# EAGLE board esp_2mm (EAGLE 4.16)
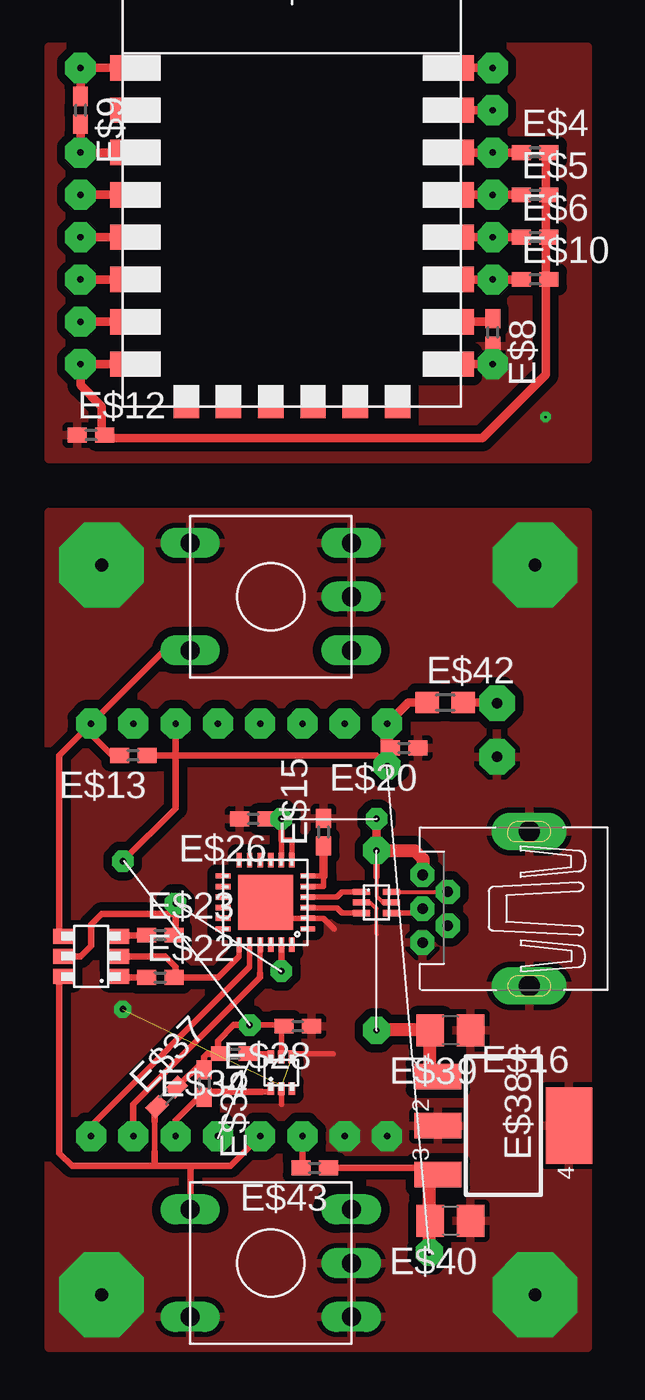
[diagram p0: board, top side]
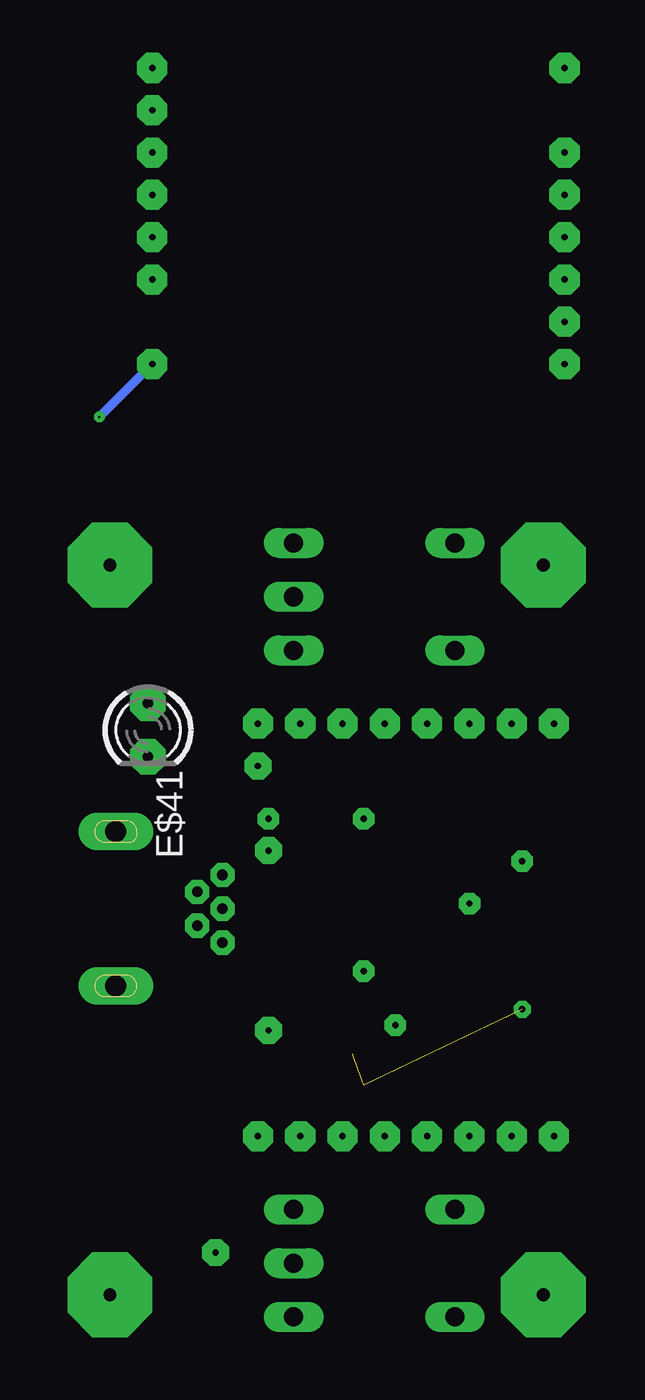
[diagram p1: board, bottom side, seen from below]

No outline drawn. Coordinates in mm, seen from the top.
Copper layers (1*16): Top 0.035mm / dielectric 1.5mm / Bottom 0.035mm
Design rules "default": minimum track width 10mil, minimum drill 24mil, track to track 8mil, track to pad 8mil, pad to pad 8mil, via to via 8mil, smd to smd 8mil, copper to edge 40mil, drill to drill 8mil, minimum pad ring 10mil, minimum via ring 8mil, stop-mask expansion 4mil, vias tented up to drill 0mil, thermal gap 10mil

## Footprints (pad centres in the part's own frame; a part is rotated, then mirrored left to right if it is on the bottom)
12E = smd 2.4 x 1.2: P$1 0.6,16; P$2 0.6,14; P$3 0.6,12; P$4 0.6,10; P$5 0.6,8; P$6 0.6,6; P$7 0.6,4; P$8 0.6,2; P$9 15.4,16; P$10 15.4,14; P$11 15.4,12; P$12 15.4,10; P$13 15.4,8; P$14 15.4,6; P$15 15.4,4; P$16 15.4,2 | smd 1.2 x 1.5: P$17 3,0.2; P$18 5,0.2; P$19 7,0.2; P$20 9,0.2; P$21 11,0.2; P$22 13,0.2
C0402 = smd 0.9 x 0.7: 1 -0.65,0; 2 0.65,0
QFN24 = smd 0.7 x 0.25: 1 -2,1.25; 2 -2,0.75; 3 -2,0.25; 4 -2,-0.25; 5 -2,-0.75; 6 -2,-1.25; 13 2,-1.25; 14 2,-0.75; 15 2,-0.25; 16 2,0.25; 17 2,0.75; 18 2,1.25 | smd 0.25 x 0.7: 7 -1.25,-2; 8 -0.75,-2; 9 -0.25,-2; 10 0.25,-2; 11 0.75,-2; 12 1.25,-2; 19 1.25,2; 20 0.75,2; 21 0.25,2; 22 -0.25,2; 23 -0.75,2; 24 -1.25,2 | smd 2.6 x 2.6: EP 0,0
32005-601 = drill 0.5 pad 1.15 octagon: 1 2.825,1.6; 2 1.625,0.8; 3 2.825,0; 4 1.625,-0.8; 5 2.825,-1.6 | drill 1 pad 1.778 long: M1 -2.225,3.65; M2 -2.225,-3.65
SUPERSOT-6 = smd 0.7 x 1: P$1 -0.95,1.3; P$2 0,1.3; P$3 0.95,1.3; P$4 -0.95,-1.3; P$5 0,-1.3; P$6 0.95,-1.3
SOT666 = smd 0.3 x 0.8: 1 0.5,0.7; 2 0,0.7; 3 -0.5,0.7; 4 -0.5,-0.7; 5 0,-0.7; 6 0.5,-0.7
SW_TACT_KSCL = drill 0.9 long: 1 -3.81,2.54; 2 -3.81,-2.54; 3 3.81,-2.54; 4 3.81,2.54; 5 -3.81,0
SOT563 = smd 0.3 x 0.6: 1 -0.5,-0.75; 2 0,-0.75; 3 0.5,-0.75; 4 0.5,0.75; 5 0,0.75; 6 -0.5,0.75
SOT223 = smd 1.219 x 2.235: 1 -2.311,-3.099; 2 0,-3.099; 3 2.311,-3.099 | smd 3.6 x 2.2: 4 0,3.099
C0805 = smd 1.3 x 1.5: 1 -0.95,0; 2 0.95,0
LED3MM = drill 0.5 pad 1.676 octagon: A -1.27,0; K 1.27,0
R0603 = smd 1.1 x 1: 1 -0.85,0; 2 0.85,0

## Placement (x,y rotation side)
E$3  [12E]  3.5,45 0 top
E$4  [C0402]  23,57 0 top
E$5  [C0402]  23,55 0 top
E$6  [C0402]  23,53 0 top
E$8  [C0402]  21,48.5 270 top
E$9  [C0402]  1.5,59 270 top
E$10  [C0402]  23,51 0 top
E$12  [C0402]  2,43.65 0 top
E$13  [C0402]  4,28.5 180 top
E$14  [QFN24]  10.25,21.55 180 top
E$15  [C0402]  13,24.88 90 top
E$16  [32005-601]  20.5,21.25 180 top
E$20  [C0402]  16.8,28.85 180 top
E$21  [SUPERSOT-6]  2,19 90 top
E$22  [C0402]  5.28,18 0 top
E$23  [C0402]  5.28,20 0 top
E$24  [SOT666]  15.5,21.55 90 top
E$25  [SW_TACT_KSCL]  10.5,4.5 180 top
E$26  [C0402]  9.68,25.5 180 top
E$27  [SOT563]  11,13.5 0 top
E$28  [C0402]  11.78,15.7 180 top
E$34  [C0402]  8.78,14.4 180 top
E$35  [C0402]  7.35,12.97 270 top
E$36  [SW_TACT_KSCL]  10.5,36 180 top
E$37  [C0402]  5.58,12.36 45 top
E$38  [SOT223]  21.5,11 270 top
E$39  [C0805]  19,15.5 180 top
E$40  [C0805]  19,6.5 180 top
E$41  [LED3MM]  21.2,29.7 270 bottom
E$42  [R0603]  18.75,31 0 top
E$43  [C0402]  12.57,9 180 top

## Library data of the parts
E$3 = esp8266
E$4-E$6 E$8-E$10 E$12 E$13 E$15 E$20 E$22 E$23 E$26 E$28 E$34 E$35 E$37-E$40 E$42 E$43 = ref-packages
E$14 = silabs
E$16 = con-cypressindustries
E$21 E$25 E$36 = sb
E$24 = st-microelectronics
E$27 = texas
E$41 = led

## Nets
GND1: E$8.2 E$12.1
GND2: E$15.2 E$16.1 E$16.M1 E$16.M2 E$20.1 E$25.1 E$25.4 E$25.5 E$26.2 E$28.1 E$36.2 E$36.3 E$36.5 E$38.2 E$38.4 E$39.1 E$40.1 E$41.K

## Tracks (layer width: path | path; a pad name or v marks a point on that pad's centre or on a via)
GND1  (via drill 0.1 pad 0.3, 0.3 pad 1.42)
  Top 0.305: v21,47 21,48
  Top 0.406: 19,47 v21,47
  Bottom 0.406: v21,47 v23.5,44.5
  pour Top (isolate 0.406): 0,42.5 25.5,42.5 25.5,62 0,62
GND2  (via drill 0.3 pad 0.81, 0.3 pad 1.42, 0.6 pad 4)  (2 unrouted)
  Top 0.2: 14.62,21.55 15.2,21.55 15.5,21.25 15.5,20.05
  Top 0.254: 11,12 11,12.9 | 13.5,20.3 13,20.8 11,20.8 | 11.55,14.4 13.45,14.4
  other vias: 2.5,3 14,10.5 16,10.5 23,3 2.5,37.5 23,37.5 3.5,16.5
  pour Top (isolate 0.406): 25.5,0.5 25.5,40 0,40 0,0.5
S$1  (via drill 0.3 pad 1.42)
  Top 0.406: 19,61 v21,61
S$7  (via drill 0.3 pad 1.42)
  Top 0.406: 19,59 v21,59
S$8  (via drill 0.3 pad 1.42)
  other vias: 21,57
S$9  (via drill 0.3 pad 1.42)
  other vias: 21,55
S$10  (via drill 0.3 pad 1.42)
  Top 0.406: v1.5,49 3.5,49
S$11  (via drill 0.3 pad 1.42)
  Top 0.406: 4,61 v1.5,61 1.5,60
S$12
  Top 0.406: 19.5,49 21,49
S$13
  Top 0.406: 19.5,53 22.5,53
S$14
  Top 0.406: 19.5,55 22,55
S$15
  Top 0.406: 19.5,57 22,57
S$16
  Top 0.406: 19,51 22,51
S$17  (via drill 0.3 pad 1.42)
  Top 0.406: 23.5,57 23.5,46.5 20.5,43.5 2.5,43.5 2.5,45 1.5,46 v1.5,47 4,47
S$18
  Top 0.406: 1.5,57 4,57
S$19  (via drill 0.3 pad 1.42)
  Top 0.406: v1.5,57 1.5,58
S$20  (via drill 0.3 pad 1.42)
  Top 0.406: v1.5,55 3.5,55
S$21  (via drill 0.3 pad 1.42)
  other vias: 21,53
S$22  (via drill 0.3 pad 1.42)
  other vias: 21,51
S$23  (via drill 0.3 pad 1.42)
  Top 0.406: v1.5,53 3.5,53
S$24  (via drill 0.3 pad 1.42)
  Top 0.406: v1.5,51 3.5,51
S$25  (via drill 0.3 pad 1.42)
  other vias: 2,30
S$27
  Top 0.305: 6,20 6,21.5
S$28
  Top 0.305: 2,30 2,29.5 3,28.5 3.5,28.5 | 0.5,20 0.5,28.5 2,30 | 2,30 5.5,33.5 7,33.5
S$29  (via drill 0.3 pad 1.42)
  other vias: 8,30
S$30  (via drill 0.3 pad 1.42)
  other vias: 14,30
S$31  (via drill 0.3 pad 1.02, 0.3 pad 1.27)
  Top 0.2: 16.25,21.55 15.8,21.55 15.5,21.85 15.5,22.75
  Top 0.305: 15.5,22.75 v15.5,24
  Top 0.406: v15.5,24 v15.5,25.5
  Top 0.61: v15.5,24 17.3,24 17.7,23.6 17.7,22.95
S$32
  Top 0.305: 4.5,20 3.5,20
S$33
  Top 0.254: 10,18.2 10,19.5
  Top 0.305: 4,10.5 4,12 10,18 10,18.2
S$34
  Top 0.254: 12.5,21.3 13.62,21.3 13.88,21.05 14.62,21.05
S$35
  Top 0.254: 12.5,21.8 13.62,21.8 13.88,22.05 14.62,22.05
S$36
  Top 0.254: 17.7,21.05 16.25,21.05
S$37
  Top 0.2: 16.38,22.05 18.82,22.05
S$38  (via drill 0.3 pad 1.42)
  Top 0.254: 10.1,12.6 10.45,12.6
  Top 0.305: v6,10.5 6,11.25 7.1,12.35 7.35,12.35 7.35,12.6 10.1,12.6
S$39  (via drill 0.3 pad 1.42)
  other vias: 4,10.5
S$42  (via drill 0.3 pad 1.42)
  other vias: 10,30
S$43  (via drill 0.3 pad 1.42)
  other vias: 12,30
S$44  (via drill 0.3 pad 1.42)
  other vias: 10,10.5
S$45  (via drill 0.3 pad 1.42)
  Top 0.305: 12,9 v12,10.5
S$46
  Top 0.305: 4.5,18 3.5,18
S$47
  Top 0.254: 11,24.5 11,23.8
  Top 0.305: 11,24.5 11,25.5
S$48  (via drill 0.3 pad 1.02)
  other vias: 11,25.5
S$49
  Top 0.254: 9.4,18.4 9.5,18.5 9.5,19.3
  Top 0.305: 2,10.5 2,11 9.4,18.4
S$50
  Top 0.254: 12.5,22.3 13,22.3 13,22.8 12.5,22.8
  Top 0.406: 13,22.8 13,23.8
S$51
  Top 0.305: 13.5,9 17.5,9
S$54  (via drill 0.3 pad 1.42)
  other vias: 4,30
S$55  (via drill 0.3 pad 1.42)
  other vias: 8,10.5
S$56  (via drill 0.3 pad 1.42)
  other vias: 2,10.5
S$57  (via drill 0.3 pad 1.02, 0.3 pad 1.42)
  Top 0.305: 6,28.5 5,28.5 | 6,28.5 v6,30 | 6,28.5 15.5,28.5 16,28 | 6,28.5 6,26 v3.5,23.5
  Top 0.406: v16,30 17,31 17.5,31
  Top 0.61: 16,28 v16,30
S$58
  Top 0.305: 6,21.5 6,21 2.5,21 2,20.5 2,19.5 1.5,19 0.5,19
S$60  (via drill 0.3 pad 1.02)
  other vias: 6,21.5
S$61
  Top 0.305: 11,19.5 11,18.3
S$62
  Top 0.305: 0.5,18 0.5,9.7 1.1,9.1 8.6,9.1 10,10.5
S$63  (via drill 0.3 pad 1.02)
  other vias: 11,18.3
S$64
  Top 0.254: 11.5,23.8 11.5,24.5 11,24.5
S$69
  Top 0.254: 11,14.5 11,15.75 9.5,15.75
S$70
  Top 0.254: 10.4,14.4 9.5,14.4 9.5,14.2
S$81
  Top 0.305: 6,18 6,18.5 5.5,19 3.5,19
S$82
  Top 0.305: 6.7,7 6.7,9.1
S$83
  Top 0.254: 5,9.75 5,11.2
  Top 0.305: 5,9.75 5,9.1 | 5,11.2 5,12
S$84
  Top 0.254: 9,19.5 9,19 8.9,18.9
  Top 0.305: 8.9,18.9 8,18 6,18
S$85
  Top 0.305: 7.15,13.9 6.15,12.9
S$86
  Top 0.61: 18,13.5 18,15.5 17.95,15.55 15.5,15.55
S$87
  Top 0.61: 18,5 18,8.5
S$88  (via drill 0.3 pad 1.27)
  other vias: 16,28
S$89  (via drill 0.3 pad 1.27)
  other vias: 15.5,15.5
S$90  (via drill 0.3 pad 1.27)
  other vias: 18,5
S$91
  Top 0.406: 19.5,31 21,31
S$92  (via drill 0.3 pad 1.02)
  Top 0.305: 7.35,13.6 7.35,14.25 7.5,14.4 8,14.4 8,15 8.75,15.75 v9.5,15.75

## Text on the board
Document: c | d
